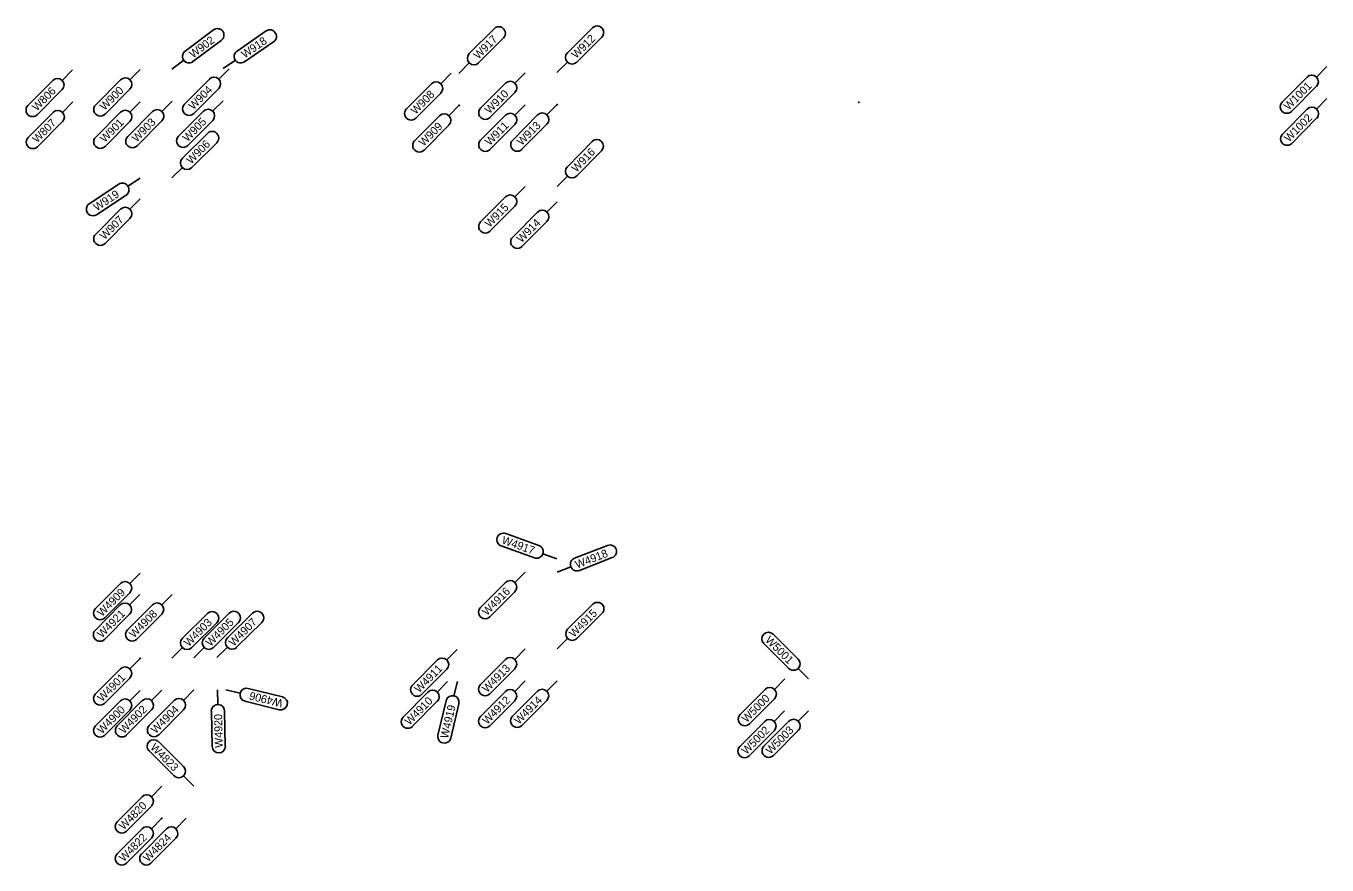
# Model space of a CAD drawing. Extents: x 12479652 to 12487250, y 9842710 to 9846560.
# Drawn here: x 12481343.8 to 12481546.9, y 9842709.6 to 9842840.7 of the extents above; entities that cross this region are included whole.
import ezdxf

# ---------------------------------------------------------------- set-up
doc = ezdxf.new("R2010")
doc.units = 0
doc.layers.add('_CIVIL_CONSTRUCTION', color=7, linetype='Continuous')
doc.layers.add('TextAlignmentLrg', color=7, linetype='Continuous')

msp = doc.modelspace()

# ---------------------------------------------------------------- linework, layer by layer
at = {"layer": '_CIVIL_CONSTRUCTION'}
for p, q in [((12481373.02, 9842840.09), (12481368.6, 9842836.79)), ((12481381.26, 9842839.93), (12481376.71, 9842836.8)), ((12481416.88, 9842840.29), (12481412.98, 9842836.39)), ((12481414.43, 9842834.94), (12481418.34, 9842838.84)), ((12481432.22, 9842840.41), (12481428.31, 9842836.52)), ((12481429.76, 9842835.06), (12481433.67, 9842838.95)), ((12481369.83, 9842835.15), (12481374.25, 9842838.45)), ((12481377.88, 9842835.11), (12481382.42, 9842838.24)), ((12481366.55, 9842833.98), (12481368.39, 9842835.36)), ((12481374.55, 9842834.08), (12481376.45, 9842835.38)), ((12481411.36, 9842833.31), (12481412.98, 9842834.93)), ((12481426.67, 9842833.45), (12481428.3, 9842835.07)), ((12481351.01, 9842833.85), (12481349.39, 9842832.22)), ((12481361.6, 9842833.94), (12481359.97, 9842832.3)), ((12481375.47, 9842834.04), (12481373.85, 9842832.41)), ((12481410.16, 9842833.32), (12481408.54, 9842831.68)), ((12481421.72, 9842833.41), (12481420.1, 9842831.77)), ((12481539.94, 9842828.82), (12481543.83, 9842832.73)), ((12481546.9, 9842834.37), (12481545.28, 9842832.74)), ((12481344.05, 9842828.3), (12481347.94, 9842832.21)), ((12481349.39, 9842830.77), (12481345.51, 9842826.85)), ((12481354.63, 9842828.39), (12481358.52, 9842832.3)), ((12481359.98, 9842830.85), (12481356.09, 9842826.94)), ((12481368.51, 9842828.5), (12481372.4, 9842832.41)), ((12481373.85, 9842830.96), (12481369.96, 9842827.05)), ((12481403.2, 9842827.77), (12481407.09, 9842831.68)), ((12481414.76, 9842827.86), (12481418.65, 9842831.77)), ((12481545.28, 9842831.29), (12481541.39, 9842827.37)), ((12481351.05, 9842828.85), (12481349.43, 9842827.22)), ((12481361.59, 9842828.88), (12481359.97, 9842827.25)), ((12481366.6, 9842828.97), (12481364.97, 9842827.34)), ((12481374.52, 9842829.04), (12481372.9, 9842827.41)), ((12481408.54, 9842830.23), (12481404.65, 9842826.32)), ((12481420.1, 9842830.32), (12481416.21, 9842826.41)), ((12481546.94, 9842829.37), (12481545.32, 9842827.74)), ((12481344.09, 9842823.3), (12481347.98, 9842827.21)), ((12481354.63, 9842823.33), (12481358.52, 9842827.25)), ((12481359.63, 9842823.43), (12481363.52, 9842827.34)), ((12481367.56, 9842823.49), (12481371.45, 9842827.4)), ((12481404.45, 9842822.78), (12481408.34, 9842826.69)), ((12481411.41, 9842828.33), (12481409.79, 9842826.69)), ((12481414.76, 9842822.86), (12481418.65, 9842826.77)), ((12481419.76, 9842822.9), (12481423.65, 9842826.81)), ((12481421.72, 9842828.41), (12481420.1, 9842826.77)), ((12481426.72, 9842828.45), (12481425.1, 9842826.81)), ((12481539.98, 9842823.82), (12481543.87, 9842827.73)), ((12481349.43, 9842825.77), (12481345.54, 9842821.85)), ((12481359.98, 9842825.8), (12481356.09, 9842821.89)), ((12481364.98, 9842825.89), (12481361.09, 9842821.98)), ((12481372.91, 9842825.95), (12481369.02, 9842822.04)), ((12481409.8, 9842825.24), (12481405.91, 9842821.33)), ((12481420.1, 9842825.32), (12481416.21, 9842821.41)), ((12481425.1, 9842825.36), (12481421.21, 9842821.45)), ((12481545.32, 9842826.29), (12481541.43, 9842822.37)), ((12481372.09, 9842823.94), (12481368.18, 9842820.05)), ((12481369.63, 9842818.59), (12481373.54, 9842822.48)), ((12481432.15, 9842822.67), (12481428.3, 9842818.72)), ((12481429.76, 9842817.29), (12481433.62, 9842821.23)), ((12481366.55, 9842816.98), (12481368.18, 9842818.6)), ((12481361.58, 9842816.96), (12481359.66, 9842815.69)), ((12481426.7, 9842815.63), (12481428.31, 9842817.27)), ((12481353.63, 9842812.94), (12481358.24, 9842815.98)), ((12481421.72, 9842815.65), (12481420.1, 9842814.01)), ((12481359.37, 9842814.27), (12481354.76, 9842811.23)), ((12481361.6, 9842813.72), (12481359.97, 9842812.09)), ((12481414.76, 9842810.1), (12481418.65, 9842814.01)), ((12481420.1, 9842812.56), (12481416.21, 9842808.65)), ((12481426.72, 9842813.26), (12481425.1, 9842811.63)), ((12481354.63, 9842808.17), (12481358.52, 9842812.09)), ((12481359.98, 9842810.64), (12481356.09, 9842806.73)), ((12481419.76, 9842807.72), (12481423.65, 9842811.63)), ((12481425.1, 9842810.18), (12481421.21, 9842806.27)), ((12481423.16, 9842757.62), (12481417.97, 9842759.49)), ((12481418.67, 9842761.42), (12481423.86, 9842759.55)), ((12481434.58, 9842759.57), (12481429.43, 9842757.57)), ((12481426.64, 9842757.46), (12481424.48, 9842758.24)), ((12481430.18, 9842755.66), (12481435.32, 9842757.65)), ((12481421.7, 9842755.41), (12481420.08, 9842753.78)), ((12481426.7, 9842755.41), (12481428.85, 9842756.24)), ((12481354.62, 9842749.7), (12481358.51, 9842753.61)), ((12481361.58, 9842755.25), (12481359.96, 9842753.61)), ((12481414.74, 9842749.86), (12481418.63, 9842753.77)), ((12481359.96, 9842752.16), (12481356.07, 9842748.25)), ((12481361.55, 9842751.89), (12481359.93, 9842750.26)), ((12481366.58, 9842751.91), (12481364.96, 9842750.28)), ((12481420.09, 9842752.33), (12481416.2, 9842748.41)), ((12481354.58, 9842746.34), (12481358.47, 9842750.26)), ((12481359.62, 9842746.36), (12481363.51, 9842750.27)), ((12481432.26, 9842750.37), (12481428.34, 9842746.48)), ((12481359.93, 9842748.81), (12481356.04, 9842744.9)), ((12481364.96, 9842748.83), (12481361.07, 9842744.92)), ((12481372.09, 9842748.94), (12481368.18, 9842745.05)), ((12481369.63, 9842743.59), (12481373.54, 9842747.48)), ((12481375.49, 9842748.96), (12481371.58, 9842745.07)), ((12481373.02, 9842743.62), (12481376.94, 9842747.51)), ((12481379.12, 9842748.99), (12481375.2, 9842745.1)), ((12481376.65, 9842743.65), (12481380.56, 9842747.54)), ((12481429.79, 9842745.03), (12481433.7, 9842748.92)), ((12481460.43, 9842745.69), (12481464.34, 9842741.81)), ((12481366.55, 9842741.97), (12481368.18, 9842743.6)), ((12481369.94, 9842742), (12481371.57, 9842743.62)), ((12481373.57, 9842742.03), (12481375.2, 9842743.65)), ((12481411.09, 9842743.3), (12481409.46, 9842741.67)), ((12481421.7, 9842743.39), (12481420.08, 9842741.76)), ((12481426.71, 9842743.41), (12481428.34, 9842745.03)), ((12481462.89, 9842740.35), (12481458.98, 9842744.24)), ((12481361.58, 9842741.92), (12481359.96, 9842740.28)), ((12481404.12, 9842737.75), (12481408.01, 9842741.67)), ((12481414.74, 9842737.84), (12481418.63, 9842741.75)), ((12481354.62, 9842736.37), (12481358.51, 9842740.28)), ((12481409.47, 9842740.22), (12481405.58, 9842736.31)), ((12481420.09, 9842740.3), (12481416.2, 9842736.39)), ((12481465.97, 9842738.73), (12481464.34, 9842740.35)), ((12481359.96, 9842738.83), (12481356.07, 9842734.92)), ((12481378.44, 9842737.22), (12481383.8, 9842735.89)), ((12481409.6, 9842738.29), (12481407.98, 9842736.66)), ((12481411.13, 9842738.3), (12481410.59, 9842736.07)), ((12481421.7, 9842738.39), (12481420.08, 9842736.75)), ((12481426.7, 9842738.43), (12481425.08, 9842736.79)), ((12481462.25, 9842738.7), (12481460.63, 9842737.07)), ((12481354.62, 9842731.37), (12481358.51, 9842735.28)), ((12481358.01, 9842731.39), (12481361.9, 9842735.31)), ((12481361.58, 9842736.92), (12481359.96, 9842735.28)), ((12481363.01, 9842731.43), (12481366.9, 9842735.35)), ((12481364.97, 9842736.94), (12481363.35, 9842735.31)), ((12481369.97, 9842736.98), (12481368.35, 9842735.35)), ((12481373.64, 9842737.01), (12481373.7, 9842734.71)), ((12481374.97, 9842737.02), (12481377.2, 9842736.47)), ((12481383.31, 9842733.9), (12481377.95, 9842735.23)), ((12481402.64, 9842732.74), (12481406.53, 9842736.66)), ((12481407.99, 9842735.21), (12481404.1, 9842731.3)), ((12481408.09, 9842729.94), (12481409.36, 9842735.3)), ((12481414.74, 9842732.84), (12481418.63, 9842736.75)), ((12481420.09, 9842735.3), (12481416.2, 9842731.39)), ((12481419.74, 9842732.88), (12481423.63, 9842736.79)), ((12481425.09, 9842735.34), (12481421.2, 9842731.43)), ((12481455.29, 9842733.16), (12481459.18, 9842737.07)), ((12481460.63, 9842735.62), (12481456.74, 9842731.71)), ((12481359.96, 9842733.83), (12481356.07, 9842729.92)), ((12481363.36, 9842733.86), (12481359.47, 9842729.95)), ((12481368.36, 9842733.9), (12481364.47, 9842729.99)), ((12481372.83, 9842728.14), (12481372.7, 9842733.66)), ((12481374.75, 9842733.71), (12481374.88, 9842728.2)), ((12481411.36, 9842734.83), (12481410.08, 9842729.46)), ((12481462.2, 9842733.7), (12481460.58, 9842732.07)), ((12481465.97, 9842733.73), (12481464.35, 9842732.1)), ((12481455.24, 9842728.15), (12481459.13, 9842732.07)), ((12481459.01, 9842728.18), (12481462.9, 9842732.1)), ((12481460.58, 9842730.62), (12481456.69, 9842726.71)), ((12481464.36, 9842730.65), (12481460.47, 9842726.74)), ((12481366.88, 9842723.57), (12481362.97, 9842727.46)), ((12481364.42, 9842728.91), (12481368.33, 9842725.02)), ((12481369.97, 9842721.95), (12481368.34, 9842723.57)), ((12481364.97, 9842721.94), (12481363.34, 9842720.3)), ((12481358, 9842716.39), (12481361.89, 9842720.3)), ((12481363.35, 9842718.85), (12481359.46, 9842714.94)), ((12481364.97, 9842716.94), (12481363.34, 9842715.3)), ((12481368.78, 9842716.94), (12481367.16, 9842715.3)), ((12481358, 9842711.39), (12481361.89, 9842715.3)), ((12481361.82, 9842711.39), (12481365.71, 9842715.3)), ((12481363.35, 9842713.85), (12481359.46, 9842709.94)), ((12481367.16, 9842713.85), (12481363.27, 9842709.94))]:
    msp.add_line(p, q, dxfattribs=at)
for centre, start, end in [((12481373.64, 9842839.27), 306.7346, 126.7346), ((12481381.84, 9842839.08), 304.4775, 124.4775), ((12481417.61, 9842839.56), 315.0121, 135.0121), ((12481432.94, 9842839.68), 314.8298, 134.8298), ((12481369.22, 9842835.97), 126.7346, 306.7346), ((12481377.29, 9842835.96), 124.4775, 304.4775), ((12481413.71, 9842835.66), 135.0121, 315.0121), ((12481429.03, 9842835.79), 134.8298, 314.8298), ((12481373.12, 9842831.69), 315.1702, 135.1702), ((12481544.56, 9842832.01), 315.1702, 135.1702), ((12481348.67, 9842831.49), 315.1702, 135.1702), ((12481359.25, 9842831.58), 315.1702, 135.1702), ((12481407.81, 9842830.96), 315.1702, 135.1702), ((12481419.38, 9842831.05), 315.1702, 135.1702), ((12481540.67, 9842828.1), 135.1702, 315.1702), ((12481344.78, 9842827.58), 135.1702, 315.1702), ((12481348.71, 9842826.49), 315.1702, 135.1702), ((12481355.36, 9842827.66), 135.1702, 315.1702), ((12481359.25, 9842826.52), 315.1702, 135.1702), ((12481364.25, 9842826.62), 315.1702, 135.1702), ((12481369.23, 9842827.77), 135.1702, 315.1702), ((12481372.18, 9842826.68), 315.1702, 135.1702), ((12481403.92, 9842827.04), 135.1702, 315.1702), ((12481409.07, 9842825.97), 315.1702, 135.1702), ((12481415.49, 9842827.13), 135.1702, 315.1702), ((12481419.38, 9842826.05), 315.1702, 135.1702), ((12481424.38, 9842826.09), 315.1702, 135.1702), ((12481544.6, 9842827.01), 315.1702, 135.1702), ((12481344.82, 9842822.58), 135.1702, 315.1702), ((12481355.36, 9842822.61), 135.1702, 315.1702), ((12481360.36, 9842822.7), 135.1702, 315.1702), ((12481368.29, 9842822.77), 135.1702, 315.1702), ((12481372.82, 9842823.21), 314.8298, 134.8298), ((12481405.18, 9842822.05), 135.1702, 315.1702), ((12481415.49, 9842822.13), 135.1702, 315.1702), ((12481420.49, 9842822.17), 135.1702, 315.1702), ((12481432.89, 9842821.95), 315.6368, 135.6368), ((12481540.71, 9842823.1), 135.1702, 315.1702), ((12481368.91, 9842819.32), 134.8298, 314.8298), ((12481429.03, 9842818.01), 135.6368, 315.6368), ((12481358.8, 9842815.13), 303.4032, 123.4032), ((12481354.2, 9842812.09), 123.4032, 303.4032), ((12481359.25, 9842811.36), 315.1702, 135.1702), ((12481419.38, 9842813.29), 315.1702, 135.1702), ((12481424.38, 9842810.91), 315.1702, 135.1702), ((12481415.49, 9842809.37), 135.1702, 315.1702), ((12481355.36, 9842807.45), 135.1702, 315.1702), ((12481420.49, 9842806.99), 135.1702, 315.1702), ((12481418.32, 9842760.45), 70.1982, 250.1982), ((12481423.51, 9842758.59), 250.1982, 70.1982), ((12481434.95, 9842758.61), 291.2159, 111.2159), ((12481429.81, 9842756.61), 111.2159, 291.2159), ((12481359.23, 9842752.89), 315.1702, 135.1702), ((12481419.36, 9842753.05), 315.1702, 135.1702), ((12481355.34, 9842748.97), 135.1702, 315.1702), ((12481359.2, 9842749.53), 315.1702, 135.1702), ((12481364.23, 9842749.55), 315.1702, 135.1702), ((12481415.47, 9842749.14), 135.1702, 315.1702), ((12481432.98, 9842749.64), 314.8298, 134.8298), ((12481372.82, 9842748.21), 314.8298, 134.8298), ((12481376.21, 9842748.24), 314.8298, 134.8298), ((12481379.84, 9842748.26), 314.8298, 134.8298), ((12481355.31, 9842745.62), 135.1702, 315.1702), ((12481360.34, 9842745.64), 135.1702, 315.1702), ((12481429.07, 9842745.75), 134.8298, 314.8298), ((12481459.7, 9842744.97), 45.1702, 225.1702), ((12481368.91, 9842744.32), 134.8298, 314.8298), ((12481372.3, 9842744.35), 134.8298, 314.8298), ((12481375.93, 9842744.37), 134.8298, 314.8298), ((12481408.74, 9842740.94), 315.1702, 135.1702), ((12481419.36, 9842741.03), 315.1702, 135.1702), ((12481463.62, 9842741.08), 225.1702, 45.1702), ((12481359.23, 9842739.56), 315.1702, 135.1702), ((12481378.2, 9842736.22), 76.1174, 256.1174), ((12481404.85, 9842737.03), 135.1702, 315.1702), ((12481415.47, 9842737.11), 135.1702, 315.1702), ((12481459.91, 9842736.34), 315.1702, 135.1702), ((12481355.34, 9842735.64), 135.1702, 315.1702), ((12481359.23, 9842734.56), 315.1702, 135.1702), ((12481362.63, 9842734.58), 315.1702, 135.1702), ((12481367.63, 9842734.62), 315.1702, 135.1702), ((12481383.55, 9842734.9), 256.1174, 76.1174), ((12481407.26, 9842735.93), 315.1702, 135.1702), ((12481410.36, 9842735.07), 346.6643, 166.6643), ((12481419.36, 9842736.03), 315.1702, 135.1702), ((12481424.36, 9842736.07), 315.1702, 135.1702), ((12481373.72, 9842733.68), 1.4265, 181.4265), ((12481456.02, 9842732.43), 135.1702, 315.1702), ((12481355.34, 9842730.64), 135.1702, 315.1702), ((12481358.74, 9842730.67), 135.1702, 315.1702), ((12481363.74, 9842730.71), 135.1702, 315.1702), ((12481403.37, 9842732.02), 135.1702, 315.1702), ((12481415.47, 9842732.11), 135.1702, 315.1702), ((12481420.47, 9842732.15), 135.1702, 315.1702), ((12481459.86, 9842731.34), 315.1702, 135.1702), ((12481463.63, 9842731.37), 315.1702, 135.1702), ((12481363.69, 9842728.18), 45.1702, 225.1702), ((12481409.09, 9842729.7), 166.6643, 346.6643), ((12481373.86, 9842728.17), 181.4265, 1.4265), ((12481455.97, 9842727.43), 135.1702, 315.1702), ((12481459.74, 9842727.46), 135.1702, 315.1702), ((12481367.61, 9842724.29), 225.1702, 45.1702), ((12481362.62, 9842719.58), 315.1702, 135.1702), ((12481358.73, 9842715.66), 135.1702, 315.1702), ((12481362.62, 9842714.58), 315.1702, 135.1702), ((12481366.43, 9842714.58), 315.1702, 135.1702), ((12481358.73, 9842710.66), 135.1702, 315.1702), ((12481362.54, 9842710.66), 135.1702, 315.1702)]:
    msp.add_arc(centre, 1.03, start, end, dxfattribs=at)
at = {"layer": 'TextAlignmentLrg'}
for centre in [(12481473.83, 9842828.8), (12481411.4, 9842828.31), (12481426.7, 9842828.43), (12481361.58, 9842741.92), (12481364.97, 9842716.94)]:
    msp.add_circle(centre, 0.05, dxfattribs=at)

# ---------------------------------------------------------------- texts
at = {"layer": '_CIVIL_CONSTRUCTION'}
for s, rotation, p in [('W902', 36.7346, (12481369.82, 9842835.63)), ('W918', 34.4775, (12481377.91, 9842835.61)), ('W917', 45.0121, (12481414.39, 9842835.44)), ('W912', 44.8298, (12481429.68, 9842835.54)), ('W806', 45.1702, (12481345.44, 9842827.34)), ('W900', 45.1702, (12481356.02, 9842827.43)), ('W904', 45.1702, (12481369.89, 9842827.53)), ('W908', 45.1702, (12481404.59, 9842826.81)), ('W910', 45.1702, (12481416.15, 9842826.9)), ('W1001', 45.1702, (12481540.95, 9842827.48)), ('W1002', 45.1702, (12481541, 9842822.49)), ('W807', 45.1702, (12481345.49, 9842822.35)), ('W901', 45.1702, (12481356.06, 9842822.41)), ('W903', 45.1702, (12481361.03, 9842822.48)), ('W905', 45.1702, (12481368.96, 9842822.54)), ('W909', 45.1702, (12481405.84, 9842821.82)), ('W911', 45.1702, (12481416.19, 9842821.94)), ('W913', 45.1702, (12481421.16, 9842821.95)), ('W906', 44.8298, (12481369.53, 9842819.05)), ('W916', 45.6368, (12481429.7, 9842817.78)), ('W919', 33.4032, (12481354.8, 9842811.73)), ('W915', 45.1702, (12481416.16, 9842809.15)), ('W907', 45.1702, (12481356.03, 9842807.23)), ('W914', 45.1702, (12481421.14, 9842806.75)), ('W4917', 340.1982, (12481417.95, 9842759.91)), ('W4918', 21.2159, (12481429.81, 9842755.93)), ('W4909', 45.1702, (12481355.62, 9842748.35)), ('W4916', 45.1702, (12481415.74, 9842748.51)), ('W4921', 45.1702, (12481355.61, 9842745.01)), ('W4908', 45.1702, (12481360.62, 9842745.01)), ('W4915', 44.8298, (12481429.31, 9842745.1)), ('W4903', 44.8298, (12481369.15, 9842743.67)), ('W4905', 44.8298, (12481372.55, 9842743.7)), ('W4907', 44.8298, (12481376.17, 9842743.72)), ('W5001', 315.1702, (12481459.11, 9842744.66)), ('W4901', 45.1702, (12481355.65, 9842735.05)), ('W4911', 45.1702, (12481405.16, 9842736.44)), ('W4913', 45.1702, (12481415.75, 9842736.49)), ('W4906', 166.1174, (12481383.96, 9842735.45)), ('W4910', 45.1702, (12481403.64, 9842731.39)), ('W4912', 45.1702, (12481415.76, 9842731.51)), ('W4914', 45.1702, (12481420.73, 9842731.52)), ('W5000', 45.1702, (12481456.29, 9842731.8)), ('W4900', 45.1702, (12481355.61, 9842730.02)), ('W4902', 45.1702, (12481359.03, 9842730.06)), ('W4904', 45.1702, (12481364, 9842730.07)), ('W4920', 91.4265, (12481374.5, 9842727.94)), ('W4919', 76.6643, (12481409.65, 9842729.32)), ('W5002', 45.1702, (12481456.26, 9842726.82)), ('W5003', 45.1702, (12481460.02, 9842726.84)), ('W4823', 315.1702, (12481363.07, 9842727.9)), ('W4820', 45.1702, (12481359, 9842715.04)), ('W4822', 45.1702, (12481359.02, 9842710.06)), ('W4824', 45.1702, (12481362.81, 9842710.03))]:
    msp.add_text(s, height=1.25, rotation=rotation, dxfattribs=at).set_placement(p)

doc.saveas('drawing.dxf')
